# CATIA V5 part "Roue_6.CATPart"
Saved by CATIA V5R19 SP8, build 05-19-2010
Part number: Roue_6
Nomenclature: 70_R6
Bounding box of the stored display mesh (mm): x -2.734 to 2.724, y -2.641 to 2.748, z 0 to 2
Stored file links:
  C:\Users\rphgr\Desktop\0_Tapis_TC520B_vitesse\Roue_6.CATPart
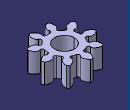
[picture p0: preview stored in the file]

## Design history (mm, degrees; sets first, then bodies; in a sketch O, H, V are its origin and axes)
External parameters (linked from other documents)
  External.Module = 0.5 mm
  External.Z = 9
  External.DiamPrimitif = 4.5 mm {= External.Module *External.Z}
  External.AnglePression = 20 deg
  External.x = 0
  External.DeportDenture = 0 mm {= External.x *External.Module}
  External.DiamBase = 4.2286 mm {= External.DiamPrimitif *cos(External.AnglePression )}
  External.DiamPied = 3.25 mm {= External.DiamPrimitif -2.5*External.Module +2*External.DeportDenture}
  External.DiamTete = 5.5 mm {= External.DiamPrimitif +2*External.Module +2*External.DeportDenture}
  External.PhiPrimitif = 0.854 deg {= atan((sin(External.ThetaPrimitif*1rad)-External.ThetaPrimitif*cos(External.ThetaPrimitif*1rad))/(cos(External.ThetaPrimitif*1rad)+External.ThetaPrimitif*sin(External.ThetaPrimitif*1rad)))}
  External.PhiTete = 7.9025 deg {= atan((sin(External.ThetaTete*1rad)-External.ThetaTete*cos(External.ThetaTete*1rad))/(cos(External.ThetaTete*1rad)+External.ThetaTete*sin(External.ThetaTete*1rad)))}
  External.PhiSymetrie = 10 deg {= 180*1 deg/(2*External.Z )}
  External.CongePied = 0.19 mm {= 0.38*External.Module}
  External.AlphaCopie = 40 deg {= 360*1 deg/External.Z}
  External.AlphaSymetrieCopie = 20 deg {= External.AlphaCopie /2}
  External.CoeffQualiteEngrenage = 7
  External.LargeurDenture = 2 mm
  External.ThetaPrimitif = 0.36397 {= sqrt(abs((External.DiamPrimitif*External.DiamPrimitif)/(External.DiamBase *External.DiamBase )-1))}
  External.ThetaTete = 0.831698 {= sqrt(abs((External.DiamTete*External.DiamTete)/(External.DiamBase *External.DiamBase )-1) )}
  External.Di = 4.3643 mm {= (External.DiamBase +External.DiamPrimitif )/2}
  External.Thetai = 0.255358 {= sqrt(abs((External.Di*External.Di)/(External.DiamBase*External.DiamBase)-1))}
  External.Phii = 0.3061 deg {= atan((sin(External.Thetai*1rad)-External.Thetai*cos(External.Thetai*1rad))/(cos(External.Thetai*1rad)+External.Thetai*sin(External.Thetai*1rad)))}
  External.Dj = 5 mm {= (External.DiamTete+External.DiamPrimitif)/2}
  External.Thetaj = 0.630965 {= sqrt(abs((External.Dj*External.Dj)/(External.DiamBase*External.DiamBase)-1))}
  External.Phij = 3.9011 deg {= atan((sin(External.Thetaj*1rad)-External.Thetaj*cos(External.Thetaj*1rad))/(cos(External.Thetaj*1rad)+External.Thetaj*sin(External.Thetaj*1rad)))}
  External.Dk = 4.2965 mm {= (External.Di+External.DiamBase)/2}
  External.Thetak = 0.179851 {= sqrt(abs((External.Dk*External.Dk)/(External.DiamBase*External.DiamBase)-1))}
  External.Phik = 0.109 deg {= atan((sin(External.Thetak*1rad)-External.Thetak*cos(External.Thetak*1rad))/(cos(External.Thetak*1rad)+External.Thetak*sin(External.Thetak*1rad)))}
  External.Dl = 4.4322 mm {= (External.DiamPrimitif+External.Di)/2}
  External.Thetal = 0.31398 {= sqrt(abs((External.Dl*External.Dl)/(External.DiamBase*External.DiamBase)-1))}
  External.Phil = 0.5585 deg {= atan((sin(External.Thetal*1rad)-External.Thetal*cos(External.Thetal*1rad))/(cos(External.Thetal*1rad)+External.Thetal*sin(External.Thetal*1rad)))}
  External.Dm = 4.75 mm {= (External.Dj+External.DiamPrimitif)/2}
  External.Thetam = 0.511664 {= sqrt(abs((External.Dm*External.Dm)/(External.DiamBase*External.DiamBase)-1))}
  External.Phim = 2.219 deg {= atan((sin(External.Thetam*1rad)-External.Thetam*cos(External.Thetam*1rad))/(cos(External.Thetam*1rad)+External.Thetam*sin(External.Thetam*1rad)))}
  External.Dn = 5.25 mm {= (External.DiamTete+External.Dj)/2}
  External.Thetan = 0.735815 {= sqrt(abs((External.Dn*External.Dn)/(External.DiamBase*External.DiamBase)-1))}
  External.Phin = 5.8129 deg {= atan((sin(External.Thetan*1rad)-External.Thetan*cos(External.Thetan*1rad))/(cos(External.Thetan*1rad)+External.Thetan*sin(External.Thetan*1rad)))}
  External.DiametreAlesage = 2 mm
Body1 (main body)
  Sketch1 on xy-plane, origin (0, 0, 0), H (1, 0, 0), V (0, 1, 0)
    construction circle A1 centre (0, 0) radius 2.25
    construction circle A2 centre (0, 0) radius 2.1143
    construction circle A3 centre (0, 0) radius 1.625
    construction circle A4 centre (0, 0) radius 2.75
    point P1 (2.1143, 0)
    construction line L1 (2.1143, 0) -> (0, 0)
    point P2 (2.2498, 0.0335)
    construction line L2 (2.2498, 0.0335) -> (0, 0)
    point P3 (2.7239, 0.3781)
    construction line L3 (2.7239, 0.3781) -> (0, 0)
    construction line L4 (2.1143, 0) -> (2.1143, 3.9367)
    point P4 (2.1143, 0)
    point P6 (1.9789, 0.0335)
    construction line L5 (2.7239, 0.3781) -> (2.2498, 0.0335)
    point P7 (2.4868, 0.2058)
    point P8 (1.7418, 0.2058)
    spline S1 through (1.7418, 0.2058) (1.9789, 0.0335) (2.1143, 0) (2.1482, 0.0041) (2.1821, 0.0117) (2.216, 0.0216) (2.2498, 0.0335) (2.3732, 0.092) (2.4942, 0.1701) (2.6115, 0.2659) (2.7239, 0.3781)
    construction line L6 (0, 0) -> (5.18, 0.9932)
    spline S2 through (1.6944, 0.453) (1.8509, 0.7008) (1.9644, 0.782) (1.9974, 0.7908) (2.0317, 0.7963) (2.0668, 0.7996) (2.1026, 0.801) (2.2389, 0.7924) (2.3802, 0.7645) (2.5246, 0.7189) (2.6706, 0.6562)
    arc A5 centre (1.8129, -0.0879) radius 0.19 from (1.9188, 0.0698) to (1.6231, -0.0787) ccw
    point P11 (1.6231, -0.0787)
    arc A6 centre (0, 0) radius 2.75 from (2.7239, 0.3781) to (2.6706, 0.6562) ccw
    point P13 (2.6706, 0.6562)
    arc A7 centre (1.6518, 0.7522) radius 0.19 from (1.4789, 0.6735) to (1.8085, 0.6448) ccw
    point P15 (1.4789, 0.6735)
    construction line L7 (0, 0) -> (3.6771, 2.1967)
    construction line L8 (0, 0) -> (5.0607, -0.8148)
    point P19 (1.395, 0.8334)
    arc A8 centre (0, 0) radius 1.625 from (1.4789, 0.6735) to (1.395, 0.8334) ccw
    point P20 (1.6043, -0.2583)
    arc A9 centre (0, 0) radius 1.625 from (1.6043, -0.2583) to (1.6231, -0.0787) ccw
    line L9 (1.395, 0.8334) -> (0, 0)
    line L10 (1.6043, -0.2583) -> (0, 0)
    construction circle A10 centre (0, 0) radius 2.1822
    construction line L11 (0, 0) -> (2.5698, 0.0137)
    point P22 (2.1821, 0.0117)
    construction circle A11 centre (0, 0) radius 2.5
    construction line L12 (0, 0) -> (4.0098, 0.2734)
    point P24 (2.4942, 0.1701)
    point P25 (2.4942, 0.1701)
    point P26 (2.3802, 0.7645)
    point P27 (2.0317, 0.7963)
    construction circle A12 centre (0, 0) radius 2.1482
    construction line L13 (0, 0) -> (48.2618, 0.0918)
    point P29 (1.9974, 0.7908)
    construction line L14 (0, 0) -> (62.8339, 12.0476)
    point P31 (2.1482, 0.0041)
    construction circle A13 centre (0, 0) radius 2.2161
    construction line L15 (0, 0) -> (57.3607, 0.5591)
    point P33 (2.216, 0.0216)
    point P34 (2.0668, 0.7996)
    construction circle A14 centre (0, 0) radius 2.375
    construction line L16 (0, 0) -> (65.6614, 2.5443)
    point P36 (2.3732, 0.092)
    point P37 (2.2389, 0.7924)
    construction circle A15 centre (0, 0) radius 2.625
    axis line L17 (0, 0) -> (59.0458, 6.0111)
    point P39 (2.5246, 0.7189)
    point P40 (2.6115, 0.2659)
    point P42 (1.7418, 0.2058)
    point P43 (1.9789, 0.0335)
    point P44 (2.1143, 0)
    point P45 (2.2498, 0.0335)
    point P46 (2.7239, 0.3781)
    point P47 (2.6706, 0.6562)
    point P48 (1.6944, 0.453)
    point P49 (2.1026, 0.801)
    point P50 (1.9644, 0.782)
    point P51 (1.8509, 0.7008)
    point P52 (2.1821, 0.0117)
    point P53 (2.4942, 0.1701)
    point P54 (2.0317, 0.7963)
    point P55 (2.3802, 0.7645)
    point P56 (2.1482, 0.0041)
    point P57 (1.9974, 0.7908)
    point P58 (2.216, 0.0216)
    point P59 (2.0668, 0.7996)
    point P60 (2.3732, 0.092)
    point P61 (2.2389, 0.7924)
    point P62 (2.6115, 0.2659)
    point P63 (2.5246, 0.7189)
    radius A1 = 2.25 {= External.DiamPrimitif /2}
    radius A2 = 2.1143 {= External.DiamBase /2}
    radius A3 = 1.625 {= External.DiamPied /2}
    radius A4 = 2.75 {= External.DiamTete /2}
    angle L2 L1 = 0.854 {= External.PhiPrimitif}
    angle L3 L1 = 7.9025 {= External.PhiTete}
    angle L4 L1 = 90
    radius A5 = 0.19 {= External.CongePied}
    radius A7 = 0.19 {= External.CongePied}
    angle L7 L6 = 20 {= External.AlphaSymetrieCopie}
    angle L2 L6 = 10 {= External.PhiSymetrie}
    radius A10 = 2.1822 {= External.Di /2}
    angle L11 L1 = 0.3061 {= External.Phii}
    radius A11 = 2.5 {= External.Dj /2}
    angle L12 L1 = 3.9011 {= External.Phij}
    radius A12 = 2.1482 {= External.Dk/2}
    angle L13 L1 = 0.109 {= External.Phik}
    angle L14 L2 = 10 {= External.PhiSymetrie}
    radius A13 = 2.2161 {= External.Dl /2}
    angle L15 L1 = 0.5585 {= External.Phil}
    radius A14 = 2.375 {= External.Dm /2}
    angle L16 L1 = 2.219 {= External.Phim}
    radius A15 = 2.625 {= External.Dn/2}
    angle L17 L1 = 5.8129 {= External.Phin}
    coincidence: P1 A2, P1 H, P2 A1, P3 A4, P4 A2, P7 L5, P42 P8, P43 P6, P44 P1, P45 L5, P45 L2, P46 L5, P46 L3, P11 A3, P47 P13, P15 A3, P19 L7, P19 A3, P20 L8, P20 A3, P3 P46, P22 L11, P22 A10, P52 P22, P24 L12, P24 A11, P53 P24, P25 P53, P54 P27, P55 P26, P31 L13, P31 A12, P56 P31, P57 P29, P33 L15, P33 A13, P58 P33, P59 P34, P36 L16, P36 A14, P60 P36, P61 P37, P40 L17, P40 A15, P62 P40, P63 P39, O L9, O L10
    horizontal: L1 H
    tangency: L4 A2, A5 A3, A5 S1, A7 A3, A7 S2, A8 A5, A9 A5
    symmetry: P6 P2 L4, P8 P7 L4, P46 P47 L6, P42 P48 L6, P45 P49 L6, P44 P50 L6, P43 P51 L6, L8 L7 L6, P26 P25 L6, P27 P22 L6, P29 P31 L14, P34 P33 L14, P37 P36 L14, P39 P40 L14
    midpoint: P7 L5
    parallelism: L9 L7, L10 L8
    concentricity: A10 A2, A11 A1
  Pad1: profile Sketch1, direction (0, 0, 1), length 2 {= External.LargeurDenture}
  CircPattern1 "Roue Dentée": of Pad1, instances 9 {= External.Z}, angular step 40 {= External.AlphaCopie}, axis from Z axis
  Body2
    Sketch2 on xy-plane, origin (0, 0, 0), H (1, 0, 0), V (0, 1, 0)
      circle A1 centre (0, 0) radius 1
      radius A1 = 1 {= External.DiametreAlesage /2}
    Pad2: profile Sketch2, direction (0, 0, 1), length 4 {= 2*External.LargeurDenture}
  Remove1: tool Body2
